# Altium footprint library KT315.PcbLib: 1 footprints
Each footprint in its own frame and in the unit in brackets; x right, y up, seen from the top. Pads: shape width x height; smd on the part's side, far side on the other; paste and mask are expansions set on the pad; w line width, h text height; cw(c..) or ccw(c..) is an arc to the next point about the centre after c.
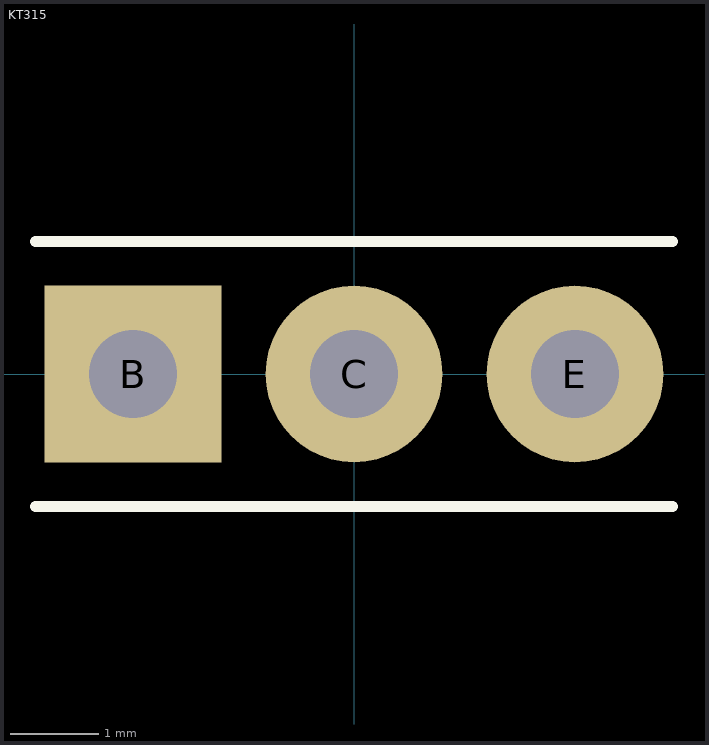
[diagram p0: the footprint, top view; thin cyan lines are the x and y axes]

## KT315 [mm]
height 5
pads (3):
  rect 2x2 hole 1: B(-2.5,0)
  round 2 hole 1: C(0,0) E(2.5,0)
Top Overlay:
  lines w0.127: -3.6,-1.5 3.6,-1.5 ; -3.6,1.5 3.6,1.5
